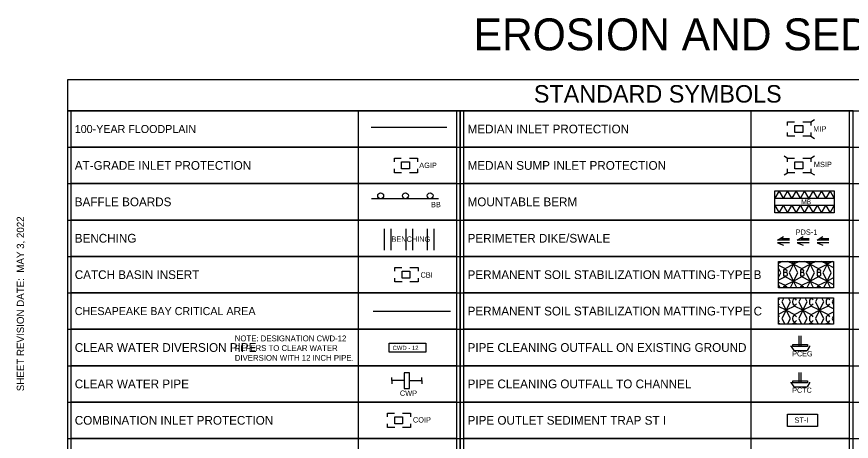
# Model space of a CAD drawing. Extents: x 1.3 to 34, y 0 to 22.5.
# Drawn here: x 1.3 to 12.78, y 15.29 to 21.12 of the extents above; entities that cross this region are included whole.
import ezdxf

# ---------------------------------------------------------------- set-up
doc = ezdxf.new("R2010")
doc.units = 0
for name, color, linetype in [('ANNO-NOTE', 7, 'Continuous'), ('ANNO-SYMB', 7, 'Continuous'), ('ANNO-TABL', 7, 'Continuous'), ('USER-LINE', 7, 'Continuous'), ('USER-TEXT', 7, 'Continuous')]:
    doc.layers.add(name, color=color, linetype=linetype)

msp = doc.modelspace()

# ---------------------------------------------------------------- linework, layer by layer
at = {"layer": 'ANNO-SYMB'}
for p, q in [((12.219, 19.674), (12.268, 19.705)), ((6.175, 19.6), (7.213, 19.6)), ((12.219, 19.475), (12.268, 19.444)), ((11.851, 19.205), (11.9, 19.174)), ((12.219, 19.174), (12.268, 19.205)), ((11.851, 18.944), (11.9, 18.975)), ((12.219, 18.975), (12.268, 18.944)), ((11.725, 18.423), (11.725, 18.727)), ((11.725, 18.727), (12.541, 18.727)), ((11.783, 18.727), (11.725, 18.626)), ((12.016, 18.727), (11.958, 18.626)), ((12.075, 18.626), (12.016, 18.727)), ((12.541, 18.727), (12.541, 18.423)), ((7.102, 18.618), (6.177, 18.618)), ((11.842, 18.626), (11.958, 18.626)), ((11.958, 18.626), (12.075, 18.626)), ((12.075, 18.626), (12.191, 18.626)), ((12.308, 18.626), (12.424, 18.626)), ((12.424, 18.626), (12.541, 18.626)), ((11.783, 18.423), (11.842, 18.524)), ((11.9, 18.423), (11.958, 18.524)), ((12.075, 18.524), (11.958, 18.524)), ((12.075, 18.524), (12.133, 18.423)), ((12.308, 18.524), (12.191, 18.524)), ((12.424, 18.524), (12.308, 18.524)), ((12.541, 18.423), (11.725, 18.423)), ((6.351, 18.206), (6.351, 17.911)), ((6.443, 18.206), (6.443, 17.911)), ((6.651, 18.206), (6.651, 17.911)), ((6.742, 18.206), (6.742, 17.911)), ((6.946, 18.206), (6.946, 17.911)), ((7.038, 18.206), (7.038, 17.911)), ((11.762, 18.049), (11.842, 18.099)), ((11.925, 18.049), (11.762, 18.049)), ((11.925, 18.069), (11.816, 18.069)), ((12.033, 18.049), (12.113, 18.099)), ((12.196, 18.049), (12.033, 18.049)), ((12.196, 18.069), (12.087, 18.069)), ((12.304, 18.049), (12.384, 18.099)), ((12.467, 18.049), (12.304, 18.049)), ((12.467, 18.069), (12.358, 18.069)), ((11.925, 18.01), (11.762, 18.01)), ((11.762, 18.01), (11.843, 17.981)), ((12.196, 18.01), (12.033, 18.01)), ((12.033, 18.01), (12.114, 17.981)), ((12.467, 18.01), (12.304, 18.01)), ((12.304, 18.01), (12.385, 17.981)), ((11.826, 17.755), (11.775, 17.73)), ((11.775, 17.704), (11.865, 17.659)), ((11.865, 17.659), (11.98, 17.717)), ((11.98, 17.717), (11.904, 17.755)), ((11.98, 17.717), (11.923, 17.602)), ((11.961, 17.755), (11.98, 17.717)), ((12.057, 17.755), (11.98, 17.717)), ((11.98, 17.717), (11.999, 17.755)), ((11.98, 17.717), (12.095, 17.659)), ((12.038, 17.602), (11.98, 17.717)), ((12.095, 17.659), (12.211, 17.717)), ((12.211, 17.717), (12.134, 17.755)), ((12.211, 17.717), (12.153, 17.602)), ((12.191, 17.755), (12.211, 17.717)), ((12.287, 17.755), (12.211, 17.717)), ((12.211, 17.717), (12.23, 17.755)), ((12.211, 17.717), (12.326, 17.659)), ((12.268, 17.602), (12.211, 17.717)), ((12.326, 17.659), (12.441, 17.717)), ((12.441, 17.717), (12.364, 17.755)), ((12.441, 17.717), (12.383, 17.602)), ((12.422, 17.755), (12.441, 17.717)), ((12.517, 17.755), (12.441, 17.717)), ((12.441, 17.717), (12.46, 17.755)), ((12.441, 17.717), (12.532, 17.672)), ((12.499, 17.602), (12.441, 17.717)), ((11.807, 17.602), (11.775, 17.666)), ((11.775, 17.537), (11.807, 17.602)), ((11.923, 17.602), (11.98, 17.487)), ((11.98, 17.487), (12.038, 17.602)), ((12.153, 17.602), (12.211, 17.487)), ((12.211, 17.487), (12.268, 17.602)), ((12.383, 17.602), (12.441, 17.487)), ((12.441, 17.487), (12.499, 17.602)), ((11.865, 17.544), (11.775, 17.499)), ((11.775, 17.474), (11.865, 17.429)), ((11.98, 17.487), (11.865, 17.544)), ((11.865, 17.429), (11.98, 17.487)), ((11.98, 17.487), (11.934, 17.395)), ((12.095, 17.544), (11.98, 17.487)), ((11.98, 17.487), (12.095, 17.429)), ((12.026, 17.395), (11.98, 17.487)), ((12.211, 17.487), (12.095, 17.544)), ((12.095, 17.429), (12.211, 17.487)), ((12.211, 17.487), (12.165, 17.395)), ((12.326, 17.544), (12.211, 17.487)), ((12.211, 17.487), (12.326, 17.429)), ((12.256, 17.395), (12.211, 17.487)), ((12.441, 17.487), (12.326, 17.544)), ((12.326, 17.429), (12.441, 17.487)), ((12.441, 17.487), (12.395, 17.395)), ((12.532, 17.532), (12.441, 17.487)), ((12.441, 17.487), (12.532, 17.441)), ((12.487, 17.395), (12.441, 17.487)), ((11.796, 17.395), (11.775, 17.436)), ((11.848, 17.255), (11.821, 17.201)), ((11.937, 17.201), (11.91, 17.255)), ((12.079, 17.255), (12.052, 17.201)), ((12.167, 17.201), (12.14, 17.255)), ((12.309, 17.255), (12.282, 17.201)), ((12.397, 17.201), (12.37, 17.255)), ((12.532, 17.24), (12.513, 17.201)), ((11.879, 17.086), (11.775, 17.138)), ((11.821, 17.201), (11.879, 17.086)), ((11.879, 17.086), (11.937, 17.201)), ((11.994, 17.144), (11.879, 17.086)), ((12.109, 17.086), (11.994, 17.144)), ((12.052, 17.201), (12.109, 17.086)), ((12.109, 17.086), (12.167, 17.201)), ((12.225, 17.144), (12.109, 17.086)), ((12.34, 17.086), (12.225, 17.144)), ((12.282, 17.201), (12.34, 17.086)), ((12.34, 17.086), (12.397, 17.201)), ((12.455, 17.144), (12.34, 17.086)), ((12.532, 17.105), (12.455, 17.144)), ((12.513, 17.201), (12.532, 17.163)), ((6.2, 17.075), (7.265, 17.075)), ((11.775, 17.034), (11.879, 17.086)), ((11.879, 17.086), (11.821, 16.971)), ((11.879, 17.086), (11.994, 17.029)), ((11.937, 16.971), (11.879, 17.086)), ((11.994, 17.029), (12.109, 17.086)), ((12.109, 17.086), (12.052, 16.971)), ((12.109, 17.086), (12.225, 17.029)), ((12.167, 16.971), (12.109, 17.086)), ((12.225, 17.029), (12.34, 17.086)), ((12.34, 17.086), (12.282, 16.971)), ((12.34, 17.086), (12.455, 17.029)), ((12.397, 16.971), (12.34, 17.086)), ((12.455, 17.029), (12.532, 17.067)), ((12.532, 17.01), (12.513, 16.971)), ((11.801, 16.895), (11.775, 16.908)), ((11.821, 16.971), (11.859, 16.895)), ((11.898, 16.895), (11.937, 16.971)), ((11.994, 16.913), (11.957, 16.895)), ((12.032, 16.895), (11.994, 16.913)), ((12.052, 16.971), (12.09, 16.895)), ((12.129, 16.895), (12.167, 16.971)), ((12.225, 16.913), (12.187, 16.895)), ((12.262, 16.895), (12.225, 16.913)), ((12.282, 16.971), (12.32, 16.895)), ((12.359, 16.895), (12.397, 16.971)), ((12.455, 16.913), (12.417, 16.895)), ((12.492, 16.895), (12.455, 16.913)), ((12.513, 16.971), (12.532, 16.933)), ((12.059, 16.588), (12.059, 16.733)), ((12.088, 16.588), (12.088, 16.733)), ((11.956, 16.588), (11.94, 16.588)), ((11.948, 16.588), (11.985, 16.534)), ((11.985, 16.534), (12.046, 16.534)), ((12.046, 16.534), (12.166, 16.534)), ((12.202, 16.588), (12.166, 16.534)), ((12.21, 16.588), (12.194, 16.588)), ((12.059, 16.088), (12.059, 16.233)), ((12.088, 16.088), (12.088, 16.233)), ((6.458, 16.12), (6.458, 16.164)), ((6.628, 16.12), (6.458, 16.12)), ((6.458, 16.12), (6.458, 16.076)), ((6.7, 16.12), (6.87, 16.12)), ((6.87, 16.12), (6.87, 16.164)), ((6.87, 16.12), (6.87, 16.076)), ((11.956, 16.088), (11.94, 16.088)), ((11.948, 16.088), (11.985, 16.034)), ((12.202, 16.088), (12.166, 16.034)), ((12.21, 16.088), (12.194, 16.088)), ((11.985, 16.034), (12.046, 16.034)), ((12.046, 16.034), (12.166, 16.034))]:
    msp.add_line(p, q, dxfattribs=at)
for points in [[(11.9, 19.624), (11.9, 19.674), (11.995, 19.674)], [(12.107, 19.674), (12.219, 19.674), (12.219, 19.624)], [(12, 19.475), (11.9, 19.475), (11.9, 19.526)], [(12.219, 19.526), (12.219, 19.475), (12.107, 19.475)], [(6.493, 19.124), (6.493, 19.174), (6.588, 19.174)], [(6.7, 19.174), (6.812, 19.174), (6.812, 19.124)], [(11.9, 19.124), (11.9, 19.174), (11.995, 19.174)], [(12.107, 19.174), (12.219, 19.174), (12.219, 19.124)], [(6.593, 18.975), (6.493, 18.975), (6.493, 19.026)], [(6.812, 19.026), (6.812, 18.975), (6.7, 18.975)], [(12, 18.975), (11.9, 18.975), (11.9, 19.026)], [(12.219, 19.026), (12.219, 18.975), (12.107, 18.975)], [(11.725, 18.626), (11.842, 18.626), (11.783, 18.727)], [(11.842, 18.626), (11.958, 18.626), (11.9, 18.727), (11.842, 18.626)], [(11.958, 18.626), (11.9, 18.727), (11.842, 18.626)], [(12.191, 18.626), (12.133, 18.727), (12.075, 18.626)], [(12.308, 18.626), (12.249, 18.727), (12.191, 18.626), (12.308, 18.626)], [(12.249, 18.727), (12.191, 18.626), (12.308, 18.626), (12.249, 18.727)], [(12.424, 18.626), (12.366, 18.727), (12.308, 18.626)], [(12.541, 18.626), (12.483, 18.727), (12.424, 18.626)], [(11.842, 18.524), (11.725, 18.524), (11.783, 18.423)], [(11.958, 18.524), (11.842, 18.524), (11.9, 18.423)], [(11.958, 18.524), (12.016, 18.423), (12.075, 18.524)], [(12.133, 18.423), (12.191, 18.524), (12.075, 18.524)], [(12.191, 18.524), (12.249, 18.423), (12.308, 18.524)], [(12.308, 18.524), (12.366, 18.423), (12.424, 18.524)], [(12.541, 18.524), (12.424, 18.524), (12.483, 18.423), (12.541, 18.524)], [(12.483, 18.423), (12.541, 18.524), (12.424, 18.524), (12.483, 18.423)], [(6.5, 17.624), (6.5, 17.674), (6.595, 17.674)], [(6.707, 17.674), (6.819, 17.674), (6.819, 17.624)], [(11.882, 17.604), (11.889, 17.612), (11.893, 17.622), (11.893, 17.625), (11.889, 17.636), (11.878, 17.642), (11.844, 17.642), (11.844, 17.558), (11.882, 17.558), (11.893, 17.564), (11.897, 17.575), (11.897, 17.585), (11.893, 17.595), (11.882, 17.604), (11.844, 17.604)], [(12.113, 17.604), (12.12, 17.612), (12.123, 17.622), (12.123, 17.625), (12.12, 17.636), (12.109, 17.642), (12.075, 17.642), (12.075, 17.558), (12.113, 17.558), (12.123, 17.564), (12.127, 17.575), (12.127, 17.585), (12.123, 17.595), (12.113, 17.604), (12.075, 17.604)], [(12.343, 17.604), (12.35, 17.612), (12.354, 17.622), (12.354, 17.625), (12.35, 17.636), (12.339, 17.642), (12.305, 17.642), (12.305, 17.558), (12.343, 17.558), (12.354, 17.564), (12.357, 17.575), (12.357, 17.585), (12.354, 17.595), (12.343, 17.604), (12.305, 17.604)], [(6.6, 17.475), (6.5, 17.475), (6.5, 17.526)], [(6.819, 17.526), (6.819, 17.475), (6.707, 17.475)], [(11.893, 17.395), (11.889, 17.406), (11.878, 17.412), (11.844, 17.412), (11.844, 17.395)], [(12.123, 17.395), (12.12, 17.406), (12.109, 17.412), (12.075, 17.412), (12.075, 17.395)], [(12.353, 17.395), (12.35, 17.406), (12.339, 17.412), (12.305, 17.412), (12.305, 17.395)], [(11.79, 17.227), (11.779, 17.241), (11.775, 17.242)], [(12.02, 17.227), (12.01, 17.241), (11.999, 17.243), (11.992, 17.243), (11.982, 17.241), (11.971, 17.227), (11.968, 17.208), (11.968, 17.199), (11.968, 17.192), (11.969, 17.186), (11.971, 17.175), (11.982, 17.162), (11.992, 17.159), (11.998, 17.159), (12.009, 17.162), (12.02, 17.175)], [(12.251, 17.227), (12.24, 17.241), (12.229, 17.243), (12.222, 17.243), (12.212, 17.241), (12.201, 17.227), (12.198, 17.208), (12.198, 17.199), (12.198, 17.192), (12.199, 17.186), (12.201, 17.175), (12.212, 17.162), (12.222, 17.159), (12.228, 17.159), (12.239, 17.162), (12.251, 17.175)], [(12.481, 17.227), (12.47, 17.241), (12.46, 17.243), (12.453, 17.243), (12.443, 17.241), (12.431, 17.227), (12.429, 17.208), (12.429, 17.199), (12.429, 17.192), (12.429, 17.186), (12.431, 17.175), (12.443, 17.162), (12.453, 17.159), (12.459, 17.159), (12.47, 17.162), (12.481, 17.175)], [(11.775, 17.161), (11.779, 17.162), (11.79, 17.175)], [(11.79, 16.997), (11.779, 17.01), (11.775, 17.012)], [(12.02, 16.997), (12.01, 17.01), (11.999, 17.013), (11.992, 17.013), (11.982, 17.01), (11.971, 16.997), (11.968, 16.978), (11.968, 16.968), (11.968, 16.962), (11.969, 16.956), (11.971, 16.945), (11.982, 16.932), (11.992, 16.929), (11.998, 16.929), (12.009, 16.932), (12.02, 16.945)], [(12.251, 16.997), (12.24, 17.01), (12.229, 17.013), (12.222, 17.013), (12.212, 17.01), (12.201, 16.997), (12.198, 16.978), (12.198, 16.968), (12.198, 16.962), (12.199, 16.956), (12.201, 16.945), (12.212, 16.932), (12.222, 16.929), (12.228, 16.929), (12.239, 16.932), (12.251, 16.945)], [(12.481, 16.997), (12.47, 17.01), (12.46, 17.013), (12.453, 17.013), (12.443, 17.01), (12.431, 16.997), (12.429, 16.978), (12.429, 16.968), (12.429, 16.962), (12.429, 16.956), (12.431, 16.945), (12.443, 16.932), (12.453, 16.929), (12.459, 16.929), (12.47, 16.932), (12.481, 16.945)], [(11.775, 16.931), (11.779, 16.932), (11.79, 16.945)], [(6.398, 15.624), (6.398, 15.674), (6.493, 15.674)], [(6.605, 15.674), (6.717, 15.674), (6.717, 15.624)], [(6.498, 15.475), (6.398, 15.475), (6.398, 15.526)], [(6.717, 15.526), (6.717, 15.475), (6.605, 15.475)]]:
    msp.add_lwpolyline(points, dxfattribs=at)
for points in [[(12, 19.624), (12.107, 19.624), (12.107, 19.526), (12, 19.526)], [(6.593, 19.124), (6.7, 19.124), (6.7, 19.026), (6.593, 19.026)], [(12, 19.124), (12.107, 19.124), (12.107, 19.026), (12, 19.026)], [(12.366, 18.423), (12.424, 18.524), (12.308, 18.524)], [(11.775, 17.755), (12.532, 17.755), (12.532, 17.395), (11.775, 17.395)], [(6.6, 17.624), (6.707, 17.624), (6.707, 17.526), (6.6, 17.526)], [(11.775, 17.255), (12.532, 17.255), (12.532, 16.895), (11.775, 16.895)], [(6.423, 16.633), (6.927, 16.633), (6.927, 16.51), (6.423, 16.51)], [(11.971, 16.617), (12.175, 16.617), (12.175, 16.588), (11.971, 16.588)], [(6.628, 16.011), (6.7, 16.011), (6.7, 16.229), (6.628, 16.229)], [(11.971, 16.117), (12.175, 16.117), (12.175, 16.088), (11.971, 16.088)], [(6.498, 15.624), (6.605, 15.624), (6.605, 15.526), (6.498, 15.526)], [(11.9, 15.661), (12.308, 15.661), (12.308, 15.489), (11.9, 15.489)]]:
    msp.add_lwpolyline(points, close=True, dxfattribs=at)
for centre in [(6.305, 18.658), (6.645, 18.658), (6.985, 18.658)]:
    msp.add_circle(centre, 0.0406, dxfattribs=at)
at = {"layer": 'ANNO-TABL'}
for p, q in [((2, 19.325), (18.2, 19.325)), ((2, 18.825), (18.2, 18.825)), ((2, 18.325), (18.2, 18.325)), ((2, 17.825), (18.2, 17.825)), ((2, 17.325), (18.2, 17.325)), ((2, 16.825), (18.2, 16.825)), ((2, 16.325), (18.2, 16.325)), ((2, 15.825), (18.2, 15.825)), ((2, 15.325), (18.2, 15.325))]:
    msp.add_line(p, q, dxfattribs=at)
for points in [[(2, 19.825), (18.2, 19.825), (18.2, 20.25), (2, 20.25)], [(2, 7.825), (7.4, 7.825), (7.4, 19.825), (2, 19.825)], [(7.4, 7.825), (12.8, 7.825), (12.8, 19.825), (7.4, 19.825)]]:
    msp.add_lwpolyline(points, close=True, dxfattribs=at)
at = {"layer": 'USER-LINE'}
for p, q in [((2.05, 19.325), (2.05, 19.825)), ((6, 19.825), (2.05, 19.825)), ((6, 19.325), (6, 19.825)), ((7.35, 19.825), (6, 19.825)), ((7.35, 19.325), (7.35, 19.825)), ((7.45, 19.325), (7.45, 19.825)), ((11.4, 19.825), (7.45, 19.825)), ((11.4, 19.325), (11.4, 19.825)), ((12.75, 19.825), (11.4, 19.825)), ((12.75, 19.325), (12.75, 19.825)), ((2.05, 18.825), (2.05, 19.325)), ((6, 19.325), (2.05, 19.325)), ((7.35, 19.325), (6, 19.325)), ((6, 18.825), (6, 19.325)), ((7.35, 18.825), (7.35, 19.325)), ((7.45, 18.825), (7.45, 19.325)), ((11.4, 19.325), (7.45, 19.325)), ((12.75, 19.325), (11.4, 19.325)), ((11.4, 18.825), (11.4, 19.325)), ((12.75, 18.825), (12.75, 19.325)), ((6, 18.825), (2.05, 18.825)), ((2.05, 18.325), (2.05, 18.825)), ((7.35, 18.825), (6, 18.825)), ((6, 18.325), (6, 18.825)), ((7.35, 18.325), (7.35, 18.825)), ((7.45, 18.325), (7.45, 18.825)), ((11.4, 18.825), (7.45, 18.825)), ((12.75, 18.825), (11.4, 18.825)), ((11.4, 18.325), (11.4, 18.825)), ((12.75, 18.325), (12.75, 18.825)), ((2.05, 17.825), (2.05, 18.325)), ((6, 18.325), (2.05, 18.325)), ((6, 17.825), (6, 18.325)), ((7.35, 18.325), (6, 18.325)), ((7.35, 17.825), (7.35, 18.325)), ((7.45, 17.825), (7.45, 18.325)), ((11.4, 18.325), (7.45, 18.325)), ((12.75, 18.325), (11.4, 18.325)), ((11.4, 17.825), (11.4, 18.325)), ((12.75, 17.825), (12.75, 18.325)), ((2.05, 17.325), (2.05, 17.825)), ((6, 17.825), (2.05, 17.825)), ((7.35, 17.825), (6, 17.825)), ((6, 17.325), (6, 17.825)), ((7.35, 17.325), (7.35, 17.825)), ((7.45, 17.325), (7.45, 17.825)), ((11.4, 17.825), (7.45, 17.825)), ((12.75, 17.825), (11.4, 17.825)), ((11.4, 17.325), (11.4, 17.825)), ((12.75, 17.325), (12.75, 17.825)), ((6, 17.325), (2.05, 17.325)), ((2.05, 16.825), (2.05, 17.325)), ((7.35, 17.325), (6, 17.325)), ((6, 16.825), (6, 17.325)), ((7.35, 16.825), (7.35, 17.325)), ((7.45, 16.825), (7.45, 17.325)), ((11.4, 17.325), (7.45, 17.325)), ((12.75, 17.325), (11.4, 17.325)), ((11.4, 16.825), (11.4, 17.325)), ((12.75, 16.825), (12.75, 17.325)), ((2.05, 16.325), (2.05, 16.825)), ((6, 16.825), (2.05, 16.825)), ((6, 16.325), (6, 16.825)), ((7.35, 16.825), (6, 16.825)), ((7.35, 16.325), (7.35, 16.825)), ((7.45, 16.325), (7.45, 16.825)), ((11.4, 16.825), (7.45, 16.825)), ((12.75, 16.825), (11.4, 16.825)), ((11.4, 16.325), (11.4, 16.825)), ((12.75, 16.325), (12.75, 16.825)), ((6, 16.325), (2.05, 16.325)), ((2.05, 15.825), (2.05, 16.325)), ((7.35, 16.325), (6, 16.325)), ((6, 15.825), (6, 16.325)), ((7.35, 15.825), (7.35, 16.325)), ((7.45, 15.825), (7.45, 16.325)), ((11.4, 16.325), (7.45, 16.325)), ((12.75, 16.325), (11.4, 16.325)), ((11.4, 15.825), (11.4, 16.325)), ((12.75, 15.825), (12.75, 16.325)), ((2.05, 15.325), (2.05, 15.825)), ((6, 15.825), (2.05, 15.825)), ((6, 15.325), (6, 15.825)), ((7.35, 15.825), (6, 15.825)), ((7.35, 15.325), (7.35, 15.825)), ((7.45, 15.325), (7.45, 15.825)), ((11.4, 15.825), (7.45, 15.825)), ((12.75, 15.825), (11.4, 15.825)), ((11.4, 15.325), (11.4, 15.825)), ((12.75, 15.325), (12.75, 15.825)), ((2.05, 14.825), (2.05, 15.325)), ((6, 15.325), (2.05, 15.325)), ((7.35, 15.325), (6, 15.325)), ((6, 14.825), (6, 15.325)), ((7.35, 14.825), (7.35, 15.325)), ((7.45, 14.825), (7.45, 15.325)), ((11.4, 15.325), (7.45, 15.325)), ((11.4, 14.825), (11.4, 15.325)), ((12.75, 15.325), (11.4, 15.325)), ((12.75, 14.825), (12.75, 15.325))]:
    msp.add_line(p, q, dxfattribs=at)

# ---------------------------------------------------------------- texts
at = {"layer": 'ANNO-NOTE'}
msp.add_text('EROSION AND SEDIMENT CONTROL (ESC) - GENERAL NOTES', height=0.4375, dxfattribs=at).set_placement((7.583, 20.656))
at = {"layer": 'ANNO-SYMB'}
for s, height, p in [('MIP', 0.0734, (12.252, 19.54)), ('AGIP', 0.0734, (6.835, 19.04)), ('MSIP', 0.0734, (12.26, 19.052)), ('MB', 0.0661, (12.086, 18.542)), ('BB', 0.0734, (6.997, 18.501)), ('PDS-1', 0.0734, (12.01, 18.122)), ('BENCHING', 0.0734, (6.453, 18.026)), ('CBI', 0.0734, (6.853, 17.535)), ('CWD - 12', 0.0588, (6.469, 16.54)), ('PCEG', 0.0714, (11.963, 16.453)), ('CWP', 0.0734, (6.569, 15.911)), ('PCTC', 0.0714, (11.963, 15.953)), ('ST-I', 0.0734, (11.993, 15.541))]:
    msp.add_text(s, height=height, dxfattribs=at).set_placement(p)
msp.add_text('COIP', height=0.0734, rotation=359.9031, dxfattribs=at).set_placement((6.748, 15.545))
at = {"layer": 'ANNO-TABL'}
for s, height, p in [('STANDARD SYMBOLS', 0.24, (8.411, 19.938)), ('100-YEAR FLOODPLAIN', 0.11, (2.1, 19.52)), ('MEDIAN INLET PROTECTION', 0.12, (7.5, 19.515)), ('AT-GRADE INLET PROTECTION', 0.12, (2.1, 19.015)), ('MEDIAN SUMP INLET PROTECTION', 0.12, (7.5, 19.015)), ('BAFFLE BOARDS', 0.12, (2.1, 18.515)), ('MOUNTABLE BERM', 0.12, (7.5, 18.515)), ('BENCHING', 0.12, (2.1, 18.015)), ('PERIMETER DIKE/SWALE', 0.12, (7.5, 18.015)), ('CATCH BASIN INSERT', 0.12, (2.1, 17.515)), ('PERMANENT SOIL STABILIZATION MATTING-TYPE B', 0.12, (7.5, 17.515)), ('CHESAPEAKE BAY CRITICAL AREA', 0.11, (2.1, 17.02)), ('PERMANENT SOIL STABILIZATION MATTING-TYPE C', 0.12, (7.5, 17.015)), ('CLEAR WATER DIVERSION PIPE', 0.12, (2.1, 16.515)), ('NOTE: DESIGNATION CWD-12', 0.08, (4.3, 16.66)), ('PIPE CLEANING OUTFALL ON EXISTING GROUND', 0.12, (7.5, 16.515)), ('REFERS TO CLEAR WATER', 0.08, (4.3, 16.527)), ('DIVERSION WITH 12 INCH PIPE.', 0.08, (4.3, 16.393)), ('CLEAR WATER PIPE', 0.12, (2.1, 16.015)), ('PIPE CLEANING OUTFALL TO CHANNEL', 0.12, (7.5, 16.015)), ('COMBINATION INLET PROTECTION', 0.12, (2.1, 15.515)), ('PIPE OUTLET SEDIMENT TRAP ST I', 0.12, (7.5, 15.515))]:
    msp.add_text(s, height=height, dxfattribs=at).set_placement(p)
at = {"layer": 'USER-TEXT'}
msp.add_text('SHEET REVISION DATE:  MAY 3, 2022', height=0.1, rotation=90, dxfattribs=at).set_placement((1.403, 15.975))

doc.saveas('drawing.dxf')
